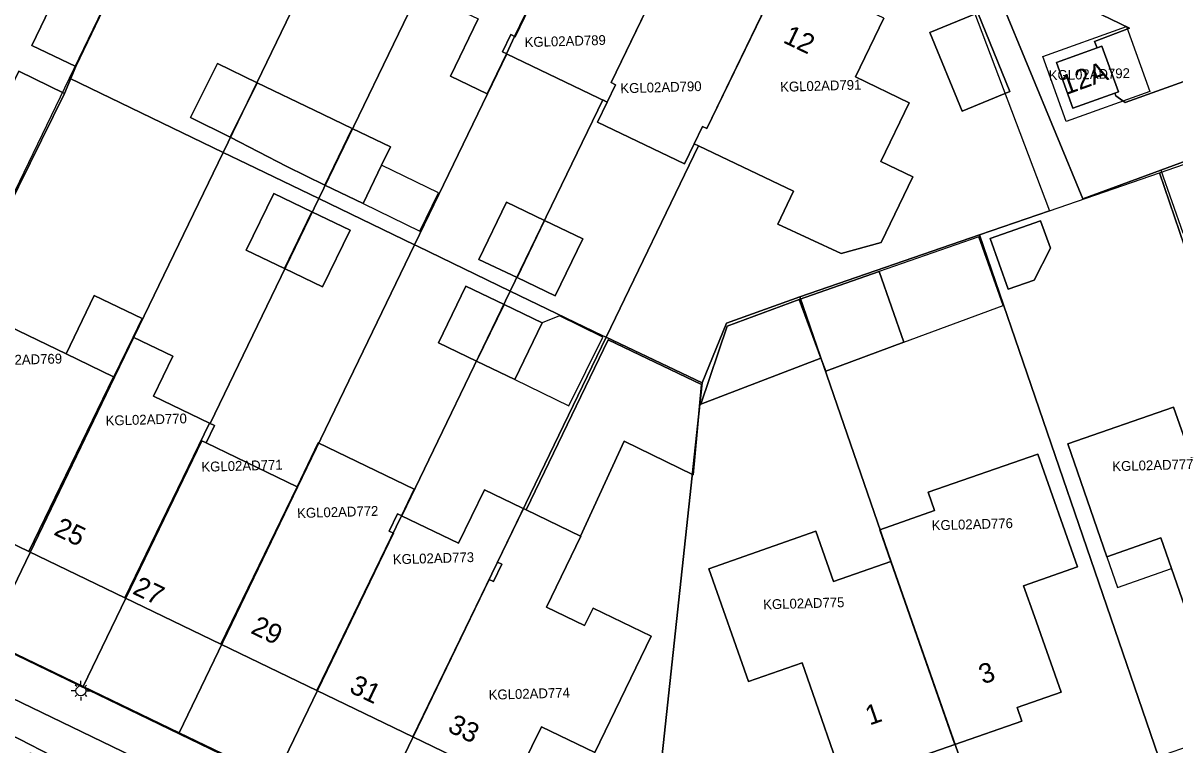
# Model space of a CAD drawing. Extents: x 124901 to 125496, y 515369 to 515789.
# Drawn here: x 125316.6 to 125375.1, y 515610.2 to 515646.9 of the extents above; entities that cross this region are included whole.
import ezdxf

# ---------------------------------------------------------------- set-up
doc = ezdxf.new("R2010")
doc.units = 0
for name, color, linetype in [('Gebouw', 7, 'Continuous'), ('Lichtmast', 7, 'Continuous'), ('Luifel', 7, 'Continuous'), ('Onbegroeid terrein', 7, 'Continuous'), ('Perceelnummers', 7, 'Continuous'), ('Perceelsgrenzen', 7, 'Continuous'), ('Scheiding', 7, 'Continuous'), ('Teksten', 7, 'Continuous'), ('Vegetatie', 7, 'Continuous'), ('Voetpad', 7, 'Continuous')]:
    doc.layers.add(name, color=color, linetype=linetype)

msp = doc.modelspace()

# ---------------------------------------------------------------- linework, layer by layer
at = {"layer": 'Gebouw'}
for points in [[(125340.197, 515643.296), (125341.175, 515645.334), (125341.595, 515646.21), (125345.479, 515654.247), (125340.612, 515656.575), (125336.732, 515648.546), (125339.74, 515647.102), (125338.342, 515644.187)], [(125346.488, 515643.861), (125350.373, 515651.906), (125345.479, 515654.247), (125341.595, 515646.21), (125341.175, 515645.334), (125346.29, 515642.87), (125346.713, 515643.753)], [(125350.706, 515640.749), (125351.13, 515641.632), (125351.356, 515641.524), (125355.242, 515649.578), (125351.29, 515651.468), (125350.373, 515651.906), (125346.488, 515643.861), (125346.713, 515643.753), (125346.29, 515642.87), (125345.801, 515641.849), (125350.217, 515639.731)], [(125352.809, 515639.754), (125355.76, 515638.339), (125354.958, 515636.667), (125358.176, 515635.182), (125360.203, 515635.731), (125361.809, 515639.081), (125360.189, 515639.858), (125361.629, 515642.839), (125358.899, 515644.157), (125360.34, 515647.14), (125357.086, 515648.696), (125355.242, 515649.578), (125351.356, 515641.524), (125351.13, 515641.632), (125350.706, 515640.749), (125350.934, 515640.653)], [(125365.112, 515647.411), (125362.686, 515646.416), (125364.324, 515642.421), (125366.75, 515643.415)], [(125371.179, 515645.624), (125369.11, 515644.89), (125369.94, 515642.56), (125372.071, 515643.326), (125372.257, 515643.393), (125371.42, 515645.71)], [(125325.137, 515642.083), (125327.151, 515641.09), (125328.511, 515643.851), (125326.496, 515644.843)], [(125331.959, 515638.653), (125333.348, 515641.537), (125331.408, 515642.467), (125328.511, 515643.851), (125327.151, 515641.09), (125330.016, 515639.593)], [(125333.348, 515641.537), (125331.959, 515638.653), (125333.901, 515637.713), (125334.836, 515639.663), (125335.288, 515640.606)], [(125329.356, 515638.228), (125327.964, 515635.354), (125329.902, 515634.418), (125331.296, 515637.301)], [(125341.719, 515633.953), (125343.115, 515636.854), (125341.174, 515637.784), (125339.782, 515634.882)], [(125333.236, 515636.373), (125331.296, 515637.301), (125329.902, 515634.418), (125331.84, 515633.481)], [(125345.055, 515635.923), (125343.115, 515636.854), (125341.719, 515633.953), (125343.655, 515633.024)], [(125368.295, 515636.844), (125365.749, 515635.936), (125366.667, 515633.363), (125367.977, 515633.83), (125368.817, 515635.45)], [(125356.036, 515632.848), (125357.145, 515629.859), (125357.391, 515629.196), (125361.367, 515630.671), (125360.1, 515634.263)], [(125339.663, 515629.706), (125341.054, 515632.588), (125339.115, 515633.524), (125337.724, 515630.641)], [(125320.246, 515633.051), (125318.812, 515630.079), (125321.22, 515628.916), (125321.245, 515628.904), (125322.225, 515630.934), (125322.68, 515631.876)], [(125310.613, 515626.746), (125313.332, 515625.432), (125311.9, 515622.46), (125316.929, 515620.031), (125321.22, 515628.916), (125318.812, 515630.079), (125313.472, 515632.658)], [(125341.054, 515632.588), (125339.663, 515629.706), (125341.601, 515628.771), (125342.992, 515631.651)], [(125357.145, 515629.859), (125356.036, 515632.848), (125352.384, 515631.494), (125351.044, 515627.525)], [(125321.245, 515628.904), (125321.22, 515628.916), (125316.929, 515620.031), (125321.804, 515617.677), (125326.095, 515626.562), (125323.255, 515627.934), (125324.235, 515629.963), (125322.225, 515630.934)], [(125342.181, 515622.149), (125344.931, 515620.821), (125347.161, 515625.65), (125350.656, 515623.934), (125351.082, 515628.52), (125346.343, 515630.8)], [(125375.063, 515627.374), (125369.695, 515625.503), (125371.671, 515619.772), (125374.406, 515620.725), (125374.949, 515619.167), (125376.301, 515615.284), (125378.556, 515616.07), (125378.79, 515615.399), (125382.17, 515616.578), (125378.931, 515625.866), (125375.951, 515624.827)], [(125325.923, 515625.557), (125326.349, 515626.439), (125326.095, 515626.562), (125321.804, 515617.677), (125326.68, 515615.322), (125330.545, 515623.325)], [(125335.847, 515621.853), (125336.498, 515623.201), (125331.622, 515625.556), (125330.545, 515623.325), (125326.68, 515615.322), (125331.555, 515612.968)], [(125368.161, 515624.989), (125362.59, 515623.046), (125362.915, 515622.113), (125360.14, 515621.146), (125360.703, 515619.532), (125363.95, 515610.227), (125367.349, 515611.413), (125367.109, 515612.102), (125369.345, 515612.882), (125367.991, 515616.739), (125367.444, 515618.296), (125370.174, 515619.255)], [(125342.036, 515622.219), (125341.96, 515622.256), (125340.063, 515623.172), (125338.747, 515620.452), (125335.847, 515621.853), (125331.555, 515612.968), (125336.431, 515610.613)], [(125341.51, 515608.16), (125342.95, 515611.13), (125345.67, 515609.82), (125348.53, 515615.73), (125345.576, 515617.156), (125345.15, 515616.273), (125343.214, 515617.208), (125344.956, 515620.809), (125344.931, 515620.821), (125342.181, 515622.149), (125342.036, 515622.219), (125336.431, 515610.613)], [(125351.455, 515619.162), (125353.465, 515613.432), (125356.192, 515614.378), (125356.733, 515612.819), (125358.075, 515608.952), (125360.315, 515609.732), (125360.555, 515609.042), (125363.95, 515610.227), (125360.703, 515619.532), (125357.783, 515618.514), (125356.895, 515621.064)]]:
    msp.add_lwpolyline(points, close=True, dxfattribs=at)
at = {"layer": 'Lichtmast'}
for p, q in [((125319.351, 515613.169), (125319.281, 515613.24)), ((125319.563, 515613.257), (125319.563, 515613.457)), ((125319.775, 515613.169), (125319.846, 515613.241)), ((125319.263, 515612.958), (125319.063, 515612.957)), ((125319.351, 515612.745), (125319.279, 515612.674)), ((125319.563, 515612.657), (125319.563, 515612.457)), ((125319.775, 515612.745), (125319.845, 515612.674)), ((125319.863, 515612.957), (125320.063, 515612.957))]:
    msp.add_line(p, q, dxfattribs=at)
msp.add_circle((125319.563, 515612.957), 0.25, dxfattribs=at)
at = {"layer": 'Luifel'}
for points in [[(125374.409, 515639.418), (125375.532, 515636.224), (125379.873, 515637.75), (125378.729, 515641.005)], [(125333.901, 515637.713), (125336.777, 515636.311), (125337.725, 515638.255), (125334.836, 515639.663)], [(125360.1, 515634.263), (125361.367, 515630.671), (125366.399, 515632.537), (125365.168, 515636.027)], [(125341.601, 515628.771), (125344.346, 515627.435), (125346.069, 515630.929), (125343.865, 515632.015), (125342.992, 515631.651)], [(125374.949, 515619.167), (125374.406, 515620.725), (125371.671, 515619.772), (125372.214, 515618.214)]]:
    msp.add_lwpolyline(points, close=True, dxfattribs=at)
at = {"layer": 'Onbegroeid terrein'}
for points in [[(125323.646, 515653.743), (125319.315, 515644.681), (125318.729, 515643.316), (125313.472, 515632.658), (125318.812, 515630.079), (125320.246, 515633.051), (125322.68, 515631.876), (125322.225, 515630.934), (125324.235, 515629.963), (125323.255, 515627.934), (125326.095, 515626.562), (125326.349, 515626.439), (125325.923, 515625.557), (125330.545, 515623.325), (125331.622, 515625.556), (125336.498, 515623.201), (125335.847, 515621.853), (125338.747, 515620.452), (125340.063, 515623.172), (125341.96, 515622.256), (125342.036, 515622.219), (125342.181, 515622.149), (125346.343, 515630.8), (125351.082, 515628.52), (125350.656, 515623.934), (125347.161, 515625.65), (125344.931, 515620.821), (125344.956, 515620.809), (125343.214, 515617.208), (125345.15, 515616.273), (125345.576, 515617.156), (125348.53, 515615.73), (125345.67, 515609.82), (125342.95, 515611.13), (125341.51, 515608.16), (125336.431, 515610.613), (125331.555, 515612.968), (125326.68, 515615.322), (125321.804, 515617.677), (125316.929, 515620.031), (125311.9, 515622.46)], [(125378.729, 515641.005), (125374.409, 515639.418), (125370.443, 515637.962), (125366.343, 515647.915)], [(125360.34, 515647.14), (125358.899, 515644.157), (125361.629, 515642.839), (125360.189, 515639.858), (125361.809, 515639.081), (125360.203, 515635.731), (125358.176, 515635.182), (125354.958, 515636.667), (125355.76, 515638.339), (125352.809, 515639.754), (125350.934, 515640.653), (125350.706, 515640.749), (125350.217, 515639.731), (125345.801, 515641.849), (125346.29, 515642.87), (125341.175, 515645.334), (125340.197, 515643.296), (125338.342, 515644.187), (125339.74, 515647.102)], [(125306.97, 515619.275), (125328.714, 515608.752)]]:
    msp.add_lwpolyline(points, dxfattribs=at)
for points in [[(125365.112, 515647.411), (125366.75, 515643.415), (125364.324, 515642.421), (125362.686, 515646.416)], [(125331.408, 515642.467), (125333.348, 515641.537), (125335.288, 515640.606), (125334.836, 515639.663), (125333.901, 515637.713), (125331.959, 515638.653), (125330.016, 515639.593), (125327.151, 515641.09), (125325.137, 515642.083), (125326.496, 515644.843), (125328.511, 515643.851)], [(125327.964, 515635.354), (125329.356, 515638.228), (125331.296, 515637.301), (125333.236, 515636.373), (125331.84, 515633.481), (125329.902, 515634.418)], [(125343.115, 515636.854), (125345.055, 515635.923), (125343.655, 515633.024), (125341.719, 515633.953), (125339.782, 515634.882), (125341.174, 515637.784)], [(125368.295, 515636.844), (125368.817, 515635.45), (125367.977, 515633.83), (125366.667, 515633.363), (125365.749, 515635.936)], [(125361.367, 515630.671), (125357.391, 515629.196), (125357.145, 515629.859), (125351.044, 515627.525), (125352.384, 515631.494), (125356.036, 515632.848), (125360.1, 515634.263)], [(125341.601, 515628.771), (125339.663, 515629.706), (125337.724, 515630.641), (125339.115, 515633.524), (125341.054, 515632.588), (125342.992, 515631.651)], [(125369.695, 515625.503), (125375.063, 515627.374), (125375.951, 515624.827), (125378.931, 515625.866), (125378.036, 515628.433), (125386.375, 515631.342), (125388.392, 515625.607), (125385.661, 515624.647), (125386.202, 515623.109), (125387.565, 515619.232), (125385.325, 515618.452), (125385.565, 515617.762), (125382.17, 515616.578), (125378.79, 515615.399), (125378.556, 515616.07), (125376.301, 515615.284), (125374.949, 515619.167), (125374.406, 515620.725), (125371.671, 515619.772)], [(125353.465, 515613.432), (125351.455, 515619.162), (125356.895, 515621.064), (125357.783, 515618.514), (125360.703, 515619.532), (125360.14, 515621.146), (125362.915, 515622.113), (125362.59, 515623.046), (125368.161, 515624.989), (125370.174, 515619.255), (125367.444, 515618.296), (125367.991, 515616.739), (125369.345, 515612.882), (125367.109, 515612.102), (125367.349, 515611.413), (125363.95, 515610.227), (125360.555, 515609.042), (125360.315, 515609.732), (125358.075, 515608.952), (125356.733, 515612.819), (125356.192, 515614.378)]]:
    msp.add_lwpolyline(points, close=True, dxfattribs=at)
at = {"layer": 'Perceelsgrenzen'}
for points in [[(125329.408, 515608.477), (125324.548, 515610.824), (125319.687, 515613.171), (125314.825, 515615.519), (125307.013, 515619.291), (125318.989, 515644.086), (125330.098, 515667.117), (125337.928, 515663.357), (125342.792, 515661.021), (125347.655, 515658.686), (125352.519, 515656.35), (125357.382, 515654.014), (125365.24, 515650.24), (125364.48, 515648.68), (125368.75, 515637.34), (125374.35, 515639.28), (125383.42, 515642.43)], [(125321.38, 515607.963), (125316.445, 515610.498), (125312.812, 515612.223), (125308.901, 515614.192), (125305.654, 515615.7), (125298.643, 515619.144), (125294.505, 515621.241), (125290.842, 515622.948), (125286.914, 515625.176), (125282.867, 515626.995), (125278.674, 515629.079)], [(125278.674, 515629.079), (125282.867, 515626.995), (125286.914, 515625.176), (125290.842, 515622.948), (125294.505, 515621.241), (125298.643, 515619.144), (125305.654, 515615.7), (125308.901, 515614.192), (125312.812, 515612.223), (125316.445, 515610.498), (125321.38, 515607.963)]]:
    msp.add_lwpolyline(points, dxfattribs=at)
for points in [[(125318.989, 515644.086), (125330.098, 515667.117), (125337.928, 515663.357), (125331.885, 515650.873), (125332.102, 515650.769), (125331.677, 515649.886), (125331.463, 515649.993), (125326.789, 515640.318)], [(125337.928, 515663.357), (125342.792, 515661.021), (125331.651, 515637.969), (125327.986, 515639.739), (125326.789, 515640.318), (125331.463, 515649.993), (125331.677, 515649.886), (125332.102, 515650.769), (125331.885, 515650.873)], [(125342.792, 515661.021), (125347.655, 515658.686), (125341.62, 515646.198), (125341.395, 515646.307), (125340.971, 515645.423), (125341.198, 515645.323), (125336.513, 515635.621), (125331.651, 515637.969)], [(125347.655, 515658.686), (125352.519, 515656.35), (125346.488, 515643.861), (125346.713, 515643.753), (125346.29, 515642.87), (125346.066, 515642.988), (125341.375, 515633.273), (125336.653, 515635.553), (125336.513, 515635.621), (125341.198, 515645.323), (125340.971, 515645.423), (125341.395, 515646.307), (125341.62, 515646.198)], [(125352.519, 515656.35), (125357.382, 515654.014), (125351.356, 515641.524), (125351.13, 515641.632), (125350.706, 515640.749), (125350.934, 515640.653), (125346.238, 515630.925), (125346.08, 515631), (125341.375, 515633.273), (125346.066, 515642.988), (125346.29, 515642.87), (125346.713, 515643.753), (125346.488, 515643.861)], [(125357.382, 515654.014), (125365.24, 515650.24), (125364.48, 515648.68), (125368.75, 515637.34), (125365.21, 515636.12), (125356.08, 515632.98), (125352.36, 515631.64), (125351.11, 515628.61), (125346.238, 515630.925), (125350.934, 515640.653), (125350.706, 515640.749), (125351.13, 515641.632), (125351.356, 515641.524)], [(125373.848, 515643.408), (125369.602, 515641.889), (125368.421, 515645.191), (125372.666, 515646.711)], [(125369.602, 515641.889), (125368.421, 515645.191), (125372.666, 515646.711), (125373.848, 515643.408)], [(125314.825, 515615.519), (125307.013, 515619.291), (125318.989, 515644.086), (125326.789, 515640.318), (125321.27, 515628.892)], [(125374.35, 515639.28), (125383.42, 515642.43), (125392.524, 515615.957), (125389.12, 515614.77), (125383.515, 515612.815), (125378.923, 515625.863)], [(125319.687, 515613.171), (125314.825, 515615.519), (125321.27, 515628.892), (125326.789, 515640.318), (125327.986, 515639.739), (125331.651, 515637.969), (125326.133, 515626.544), (125326.349, 515626.439), (125325.923, 515625.557), (125325.707, 515625.661)], [(125374.301, 515609.602), (125365.21, 515636.12), (125368.75, 515637.34), (125374.35, 515639.28), (125378.923, 515625.863), (125383.515, 515612.815)], [(125319.687, 515613.171), (125325.707, 515625.661), (125325.923, 515625.557), (125326.349, 515626.439), (125326.133, 515626.544), (125331.651, 515637.969), (125336.513, 515635.621), (125330.57, 515623.313), (125324.548, 515610.824)], [(125365.292, 515606.46), (125360.724, 515619.519), (125356.08, 515632.98), (125365.21, 515636.12), (125374.301, 515609.602)], [(125329.408, 515608.477), (125324.548, 515610.824), (125330.57, 515623.313), (125336.513, 515635.621), (125336.653, 515635.553), (125341.375, 515633.273), (125335.859, 515621.848), (125335.643, 515621.952), (125335.217, 515621.069), (125335.433, 515620.965)], [(125334.269, 515606.129), (125329.408, 515608.477), (125335.433, 515620.965), (125335.217, 515621.069), (125335.643, 515621.952), (125335.859, 515621.848), (125341.375, 515633.273), (125346.08, 515631), (125346.238, 515630.925), (125340.722, 515619.499), (125340.938, 515619.395), (125340.512, 515618.512), (125340.296, 515618.617)], [(125347.97, 515600.42), (125348.96, 515608.6), (125351.11, 515628.61), (125352.36, 515631.64), (125356.08, 515632.98), (125360.724, 515619.519), (125365.292, 515606.46)], [(125334.269, 515606.129), (125340.296, 515618.617), (125340.512, 515618.512), (125340.938, 515619.395), (125340.722, 515619.499), (125346.238, 515630.925), (125351.11, 515628.61), (125348.96, 515608.6), (125347.97, 515600.42), (125346.87, 515600.05)]]:
    msp.add_lwpolyline(points, close=True, dxfattribs=at)
at = {"layer": 'Scheiding'}
for points in [[(125319.315, 515644.681), (125323.646, 515653.743)], [(125313.472, 515632.658), (125318.729, 515643.316)]]:
    msp.add_lwpolyline(points, dxfattribs=at)
at = {"layer": 'Vegetatie'}
for points in [[(125317.069, 515645.757), (125319.315, 515644.681), (125323.646, 515653.743), (125326.5, 515659.66), (125330.185, 515667.171), (125327.914, 515668.261)], [(125318.729, 515643.316), (125316.42, 515644.448), (125304.81, 515620.318), (125306.97, 515619.275), (125310.613, 515626.746), (125313.472, 515632.658)], [(125317.991, 515609.319), (125322.28, 515607.264), (125323.183, 515609.153), (125308.913, 515616.039), (125307.036, 515612.117), (125307.775, 515611.76), (125315.999, 515607.807), (125316.985, 515609.801)]]:
    msp.add_lwpolyline(points, close=True, dxfattribs=at)
msp.add_lwpolyline([(125381.355, 515645.99), (125372.6, 515642.854), (125372.125, 515643.186), (125372.071, 515643.326), (125369.94, 515642.56), (125369.11, 515644.89), (125371.179, 515645.624), (125371.051, 515645.953), (125372.825, 515646.633), (125365.266, 515650.293), (125364.528, 515648.779), (125365.112, 515647.411), (125366.343, 515647.915), (125370.443, 515637.962), (125374.409, 515639.418), (125378.729, 515641.005)], dxfattribs=at)
at = {"layer": 'Voetpad'}
msp.add_lwpolyline([(125319.315, 515644.681), (125317.069, 515645.757), (125327.914, 515668.261), (125326.105, 515669.084), (125322.863, 515662.362), (125316.324, 515648.993), (125313.438, 515643.127), (125305.851, 515627.269), (125302.923, 515621.29), (125304.81, 515620.318), (125316.42, 515644.448), (125318.729, 515643.316)], close=True, dxfattribs=at)
for points in [[(125365.266, 515650.293), (125372.825, 515646.633), (125371.051, 515645.953), (125371.179, 515645.624), (125371.42, 515645.71), (125372.257, 515643.393), (125372.071, 515643.326), (125372.125, 515643.186), (125372.6, 515642.854), (125381.355, 515645.99)], [(125328.714, 515608.752), (125306.97, 515619.275), (125304.81, 515620.318), (125302.923, 515621.29), (125298.512, 515623.527), (125297.778, 515622.348), (125297.599, 515621.726), (125297.59, 515621.559), (125301.997, 515619.4), (125301.03, 515617.479), (125301.475, 515617.255), (125300.518, 515615.355), (125300.866, 515615.148), (125301.821, 515614.657), (125302.797, 515616.59), (125303.776, 515618.529), (125306.105, 515617.417), (125308.913, 515616.039), (125323.183, 515609.153)]]:
    msp.add_lwpolyline(points, dxfattribs=at)

# ---------------------------------------------------------------- texts
at = {"layer": 'Perceelnummers'}
for s, rotation, p in [('KGL02AD789', 1.63386, (125342.107, 515645.665)), ('KGL02AD792', 1.63417, (125368.726, 515643.981)), ('KGL02AD791', 1.63401, (125355.085, 515643.394)), ('KGL02AD790', 1.63392, (125346.97, 515643.32)), ('KGL02AD769', 1.63354, (125314.492, 515629.476)), ('KGL02AD770', 1.63361, (125320.829, 515626.434)), ('KGL02AD771', 1.63367, (125325.691, 515624.085)), ('KGL02AD777', 1.63421, (125371.954, 515624.115)), ('KGL02AD772', 1.63373, (125330.553, 515621.735)), ('KGL02AD776', 1.6341, (125362.782, 515621.113)), ('KGL02AD773', 1.63378, (125335.414, 515619.386)), ('KGL02AD775', 1.634, (125354.222, 515617.093)), ('KGL02AD774', 1.63384, (125340.281, 515612.502))]:
    msp.add_text(s, height=0.5, rotation=rotation, dxfattribs=at).set_placement(p)
at = {"layer": 'Teksten'}
for s, rotation, p in [('12', 334.4, (125355.175, 515645.924)), ('12A', 19.9, (125369.576, 515643.22)), ('25', 334.2, (125318.138, 515620.913)), ('27', 334.2, (125322.138, 515617.913)), ('29', 334.2, (125328.138, 515615.913)), ('3', 19.2, (125365.377, 515613.276)), ('31', 334.2, (125333.138, 515612.913)), ('1', 19.2, (125359.621, 515611.19)), ('33', 334.2, (125338.138, 515610.913))]:
    msp.add_text(s, height=1, rotation=rotation, dxfattribs=at).set_placement(p)

doc.saveas('drawing.dxf')
